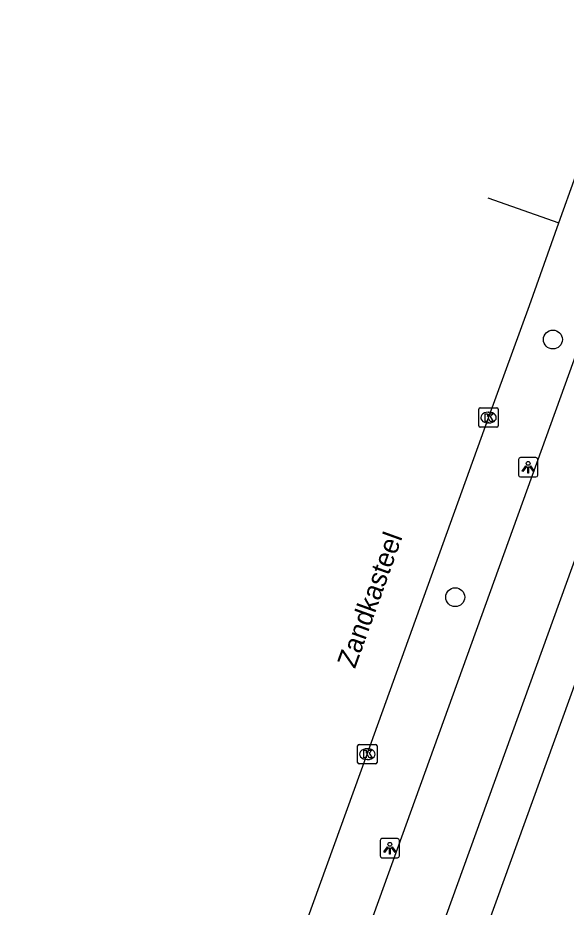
# Model space of a CAD drawing. Extents: x 156664 to 157568, y 383571 to 384421.
# Drawn here: x 156792.6 to 156820.91, y 384249.71 to 384295.66 of the extents above; entities that cross this region are included whole.
import ezdxf

# ---------------------------------------------------------------- set-up
doc = ezdxf.new("R2010")
doc.units = 0
for name, color, linetype in [('IMGEO_Boom', 7, 'Continuous'), ('IMGEO_Fietspad_open', 7, 'Continuous'), ('IMGEO_Kolk', 7, 'Continuous'), ('IMGEO_Lichtpunt', 7, 'Continuous'), ('IMGEO_Openbare_ruimte_label', 7, 'Continuous'), ('IMGEO_Rijbaan_lokaal_gesloten', 7, 'Continuous'), ('IMGEO_Rijbaan_lokaal_open', 7, 'Continuous'), ('IMGEO_Voetpad_open', 7, 'Continuous')]:
    doc.layers.add(name, color=color, linetype=linetype)

msp = doc.modelspace()

# ---------------------------------------------------------------- linework, layer by layer
at = {"layer": 'IMGEO_Boom'}
for centre in [(156820.228, 384279.042), (156815.184, 384265.729)]:
    msp.add_circle(centre, 0.489, dxfattribs=at)
at = {"layer": 'IMGEO_Fietspad_open'}
for points in [[(156833.031, 384293.583), (156831.476, 384295.664), (156797.885, 384202.753), (156781.915, 384158.669), (156778.633, 384149.604), (156765.945, 384114.759), (156745.635, 384058.756), (156737.507, 384036.302), (156716.373, 383978.18), (156709.217, 383958.49), (156701.659, 383937.694), (156690.408, 383906.735), (156677.045, 383870.138), (156675.34, 383865.46)], [(156795.883, 384207.536), (156822.516, 384281.28)]]:
    msp.add_lwpolyline(points, dxfattribs=at)
at = {"layer": 'IMGEO_Kolk'}
for p, q in [((156816.477, 384275.509), (156817.329, 384275.509)), ((156816.402, 384274.583), (156816.402, 384275.435)), ((156816.89, 384275.289), (156816.915, 384275.289)), ((156817.403, 384275.435), (156817.403, 384274.583)), ((156816.913, 384274.729), (156816.888, 384274.729)), ((156817.329, 384274.509), (156816.477, 384274.509)), ((156810.146, 384257.196), (156810.146, 384258.048)), ((156810.221, 384258.122), (156811.073, 384258.122)), ((156811.147, 384258.048), (156811.147, 384257.196)), ((156810.634, 384257.902), (156810.659, 384257.902)), ((156811.073, 384257.122), (156810.221, 384257.122)), ((156810.657, 384257.342), (156810.632, 384257.342))]:
    msp.add_line(p, q, dxfattribs=at)
for points in [[(156816.477, 384275.509), (156817.329, 384275.509)], [(156816.402, 384274.583), (156816.402, 384275.435)], [(156816.723, 384275.209), (156816.846, 384275.209), (156816.846, 384275.058), (156816.976, 384275.209), (156817.14, 384275.209), (156816.994, 384275.058), (156817.147, 384274.809), (156816.995, 384274.809), (156816.91, 384274.973), (156816.846, 384274.906), (156816.846, 384274.809), (156816.723, 384274.809), (156816.723, 384275.209)], [(156817.403, 384275.435), (156817.403, 384274.583)], [(156817.329, 384274.509), (156816.477, 384274.509)], [(156810.146, 384257.196), (156810.146, 384258.048)], [(156810.221, 384258.122), (156811.073, 384258.122)], [(156811.147, 384258.048), (156811.147, 384257.196)], [(156810.467, 384257.822), (156810.59, 384257.822), (156810.59, 384257.671), (156810.72, 384257.822), (156810.884, 384257.822), (156810.738, 384257.671), (156810.891, 384257.422), (156810.739, 384257.422), (156810.654, 384257.586), (156810.59, 384257.519), (156810.59, 384257.422), (156810.467, 384257.422), (156810.467, 384257.822)], [(156811.073, 384257.122), (156810.221, 384257.122)]]:
    msp.add_lwpolyline(points, dxfattribs=at)
for centre, start, end in [((156816.479, 384275.433), 91.552, 178.448), ((156816.479, 384275.433), 91.552, 178.448), ((156817.327, 384275.433), 1.552, 88.448), ((156817.327, 384275.433), 1.552, 88.448), ((156816.479, 384274.585), 181.552, 268.448), ((156816.479, 384274.585), 181.552, 268.448), ((156817.327, 384274.585), 271.552, 358.448), ((156817.327, 384274.585), 271.552, 358.448), ((156810.223, 384258.046), 91.552, 178.448), ((156810.223, 384258.046), 91.552, 178.448), ((156811.071, 384258.046), 1.552, 88.448), ((156811.071, 384258.046), 1.552, 88.448), ((156810.223, 384257.198), 181.552, 268.448), ((156810.223, 384257.198), 181.552, 268.448), ((156811.071, 384257.198), 271.552, 358.448), ((156811.071, 384257.198), 271.552, 358.448)]:
    msp.add_arc(centre, 0.0765, start, end, dxfattribs=at)
for centre, major_axis, ratio, start_param, end_param in [((156816.889, 384275.009), (-0.387, 0.002), 0.722429, 4.712389, 7.853982), ((156816.914, 384275.009), (-0.39, 0.002), 0.717154, 1.570796, 4.712389), ((156810.633, 384257.622), (-0.387, 0.002), 0.722429, 4.712389, 7.853982), ((156810.658, 384257.622), (-0.39, 0.002), 0.717154, 1.570796, 4.712389)]:
    msp.add_ellipse(centre, major_axis=major_axis, ratio=ratio, start_param=start_param, end_param=end_param, dxfattribs=at)
at = {"layer": 'IMGEO_Lichtpunt'}
for p, q in [((156818.452, 384272.845), (156818.452, 384272.038)), ((156818.452, 384272.845), (156818.452, 384272.038)), ((156819.354, 384272.94), (156818.546, 384272.94)), ((156819.354, 384272.94), (156818.546, 384272.94)), ((156819.448, 384272.038), (156819.448, 384272.845)), ((156819.448, 384272.038), (156819.448, 384272.845)), ((156818.546, 384271.944), (156819.354, 384271.944)), ((156818.546, 384271.944), (156819.354, 384271.944)), ((156811.309, 384253.165), (156811.309, 384252.358)), ((156811.309, 384253.165), (156811.309, 384252.358)), ((156812.211, 384253.26), (156811.403, 384253.26)), ((156812.211, 384253.26), (156811.403, 384253.26)), ((156812.305, 384252.358), (156812.305, 384253.165)), ((156812.305, 384252.358), (156812.305, 384253.165)), ((156811.403, 384252.264), (156812.211, 384252.264)), ((156811.403, 384252.264), (156812.211, 384252.264))]:
    msp.add_line(p, q, dxfattribs=at)
for points in [[(156818.826, 384272.509), (156818.865, 384272.481), (156818.677, 384272.219), (156818.639, 384272.246), (156818.826, 384272.509)], [(156818.928, 384272.461), (156818.975, 384272.461), (156818.975, 384272.139), (156818.928, 384272.139), (156818.928, 384272.461)], [(156819.038, 384272.481), (156819.076, 384272.508), (156819.263, 384272.246), (156819.224, 384272.218), (156819.038, 384272.481)], [(156811.683, 384252.829), (156811.722, 384252.801), (156811.534, 384252.539), (156811.496, 384252.566), (156811.683, 384252.829)], [(156811.785, 384252.781), (156811.832, 384252.781), (156811.832, 384252.459), (156811.785, 384252.459), (156811.785, 384252.781)], [(156811.895, 384252.801), (156811.933, 384252.828), (156812.12, 384252.566), (156812.081, 384252.538), (156811.895, 384252.801)]]:
    msp.add_lwpolyline(points, dxfattribs=at)
for centre in [(156818.951, 384272.643), (156811.808, 384252.963)]:
    msp.add_circle(centre, 0.0994, dxfattribs=at)
for centre, start, end in [((156818.546, 384272.845), 90, 180), ((156818.546, 384272.845), 90, 180), ((156819.354, 384272.845), 0, 90), ((156819.354, 384272.845), 0, 90), ((156818.546, 384272.038), 180, 270), ((156818.546, 384272.038), 180, 270), ((156819.354, 384272.038), 270, 0), ((156819.354, 384272.038), 270, 360), ((156811.403, 384253.165), 90, 180), ((156811.403, 384253.165), 90, 180), ((156812.211, 384253.165), 0, 90), ((156812.211, 384253.165), 0, 90), ((156811.403, 384252.358), 180, 270), ((156811.403, 384252.358), 180, 270), ((156812.211, 384252.358), 270, 0), ((156812.211, 384252.358), 270, 360)]:
    msp.add_arc(centre, 0.0946, start, end, dxfattribs=at)
at = {"layer": 'IMGEO_Rijbaan_lokaal_gesloten'}
for points in [[(156820.538, 384285.07), (156821.409, 384287.513)], [(156816.868, 384286.362), (156820.538, 384285.07)]]:
    msp.add_lwpolyline(points, dxfattribs=at)
at = {"layer": 'IMGEO_Rijbaan_lokaal_open'}
msp.add_lwpolyline([(156793.474, 384210.156), (156793.934, 384211.426), (156795.01, 384214.401), (156798.075, 384222.87), (156804.351, 384240.236), (156807.886, 384250), (156810.646, 384257.622), (156816.899, 384274.997), (156819.013, 384280.795), (156820.538, 384285.07)], dxfattribs=at)
at = {"layer": 'IMGEO_Voetpad_open'}
msp.add_lwpolyline([(156814.804, 384186.583), (156800.216, 384202.772), (156824.508, 384269.917), (156831.616, 384229.116)], dxfattribs=at)

# ---------------------------------------------------------------- texts
at = {"layer": 'IMGEO_Openbare_ruimte_label'}
msp.add_text('Zandkasteel', height=1, rotation=70.1882, dxfattribs=at).set_placement((156810.006, 384262.004))

doc.saveas('drawing.dxf')
